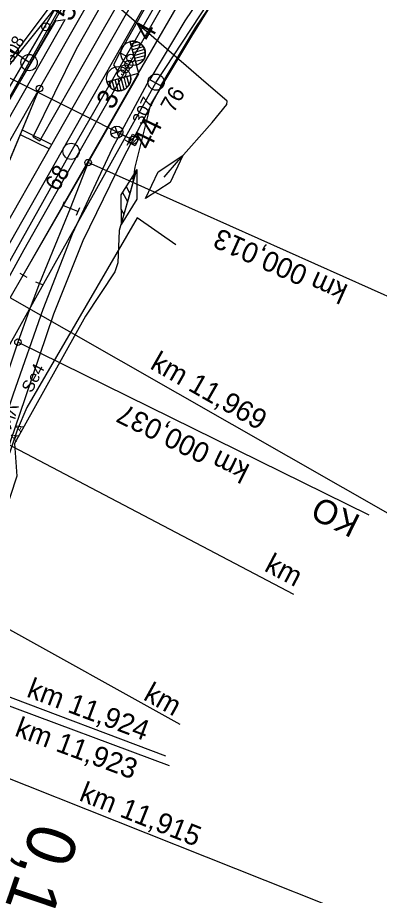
# Model space of a CAD drawing. Extents: x -598638 to -597933, y -1164002 to -1161904.
# Drawn here: x -598180.3 to -598135.8, y -1162996.2 to -1162888 of the extents above; entities that cross this region are included whole.
import ezdxf

# ---------------------------------------------------------------- set-up
doc = ezdxf.new("R2010")
doc.units = 0
for name, color, linetype in [('Vrstva 1', 7, 'Continuous'), ('Vrstva 11', 7, 'Continuous'), ('Vrstva 12', 7, 'Continuous'), ('Vrstva 17', 7, 'Continuous'), ('Vrstva 2', 7, 'Continuous'), ('Vrstva 25', 7, 'Continuous'), ('Vrstva 26', 7, 'Continuous'), ('Vrstva 28', 7, 'Continuous'), ('Vrstva 3', 7, 'Continuous'), ('Vrstva 31', 7, 'Continuous'), ('Vrstva 4', 7, 'Continuous'), ('Vrstva 43', 7, 'Continuous'), ('Vrstva 44', 7, 'Continuous'), ('Vrstva 51', 7, 'Continuous'), ('Vrstva 6', 7, 'Continuous'), ('Vrstva 63', 7, 'Continuous'), ('Vrstva 7', 7, 'Continuous')]:
    doc.layers.add(name, color=color, linetype=linetype)

msp = doc.modelspace()

# ---------------------------------------------------------------- linework, layer by layer
at = {"layer": 'Vrstva 1'}
for p, q in [((-598183.34, -1162910.45), (-598177.65, -1162896.76)), ((-598128.48, -1162925.23), (-598171.66, -1162905.9)), ((-598181.24, -1162922.58), (-598179.64, -1162919.76)), ((-598122.64, -1162956.06), (-598181.24, -1162922.58)), ((-598137.06, -1162949.35), (-598180.29, -1162928.03)), ((-598210.16, -1162970.38), (-598089.89, -1163018.24))]:
    msp.add_line(p, q, dxfattribs=at)
for points in [[(-598185.54, -1162920.23), (-598173.48, -1162899.03), (-598147.83, -1162853.98), (-598130.65, -1162823.79), (-598124.88, -1162813.62), (-598094.68, -1162760.58), (-598072.51, -1162721.65)], [(-598179.64, -1162919.76), (-598169.47, -1162901.95), (-598165.44, -1162894.88), (-598159.18, -1162883.99), (-598151.26, -1162869.97), (-598148.35, -1162864.87)], [(-598184.99, -1162909.66), (-598177.65, -1162896.76), (-598171.54, -1162886.04)], [(-598171.66, -1162905.9), (-598173.85, -1162911.56), (-598177.66, -1162920.77), (-598178.92, -1162924.14), (-598179.73, -1162926.43), (-598180.29, -1162928.03)], [(-598180.29, -1162928.03), (-598182.13, -1162933.48), (-598183.24, -1162936.76), (-598184.09, -1162939.28), (-598186.44, -1162946.2), (-598190.32, -1162957.65), (-598194.22, -1162969.2), (-598198.16, -1162980.82), (-598202.12, -1162992.49)]]:
    msp.add_lwpolyline(points, dxfattribs=at)
for centre in [(-598171.66, -1162905.9), (-598180.29, -1162928.03)]:
    msp.add_circle(centre, 0.4, dxfattribs=at)
at = {"layer": 'Vrstva 11'}
for p, q in [((-598166.55, -1162903.3), (-598165.91, -1162902.66)), ((-598166.29, -1162903.57), (-598165.64, -1162902.92))]:
    msp.add_line(p, q, dxfattribs=at)
msp.add_lwpolyline([(-598181.56, -1162895.33), (-598166.09, -1162903.12)], dxfattribs=at)
msp.add_circle((-598166.09, -1162903.12), 0.5, dxfattribs=at)
at = {"layer": 'Vrstva 12'}
msp.add_lwpolyline([(-598166.69, -1162903.41), (-598166.21, -1162902.41), (-598165.38, -1162902.84), (-598165.88, -1162903.83), (-598166.69, -1162903.41)], dxfattribs=at)
at = {"layer": 'Vrstva 17'}
msp.add_lwpolyline([(-598160.87, -1162916.03), (-598165.61, -1162912.69), (-598173.23, -1162925.77), (-598179.2, -1162936.08), (-598180.4, -1162938.88), (-598184.23, -1162950.26), (-598188.1, -1162961.63), (-598191.91, -1162973.02), (-598198.54, -1162970.75), (-598204.12, -1162984.71), (-598208.62, -1162995.88), (-598214.21, -1163009.83), (-598215.03, -1163012.69), (-598218.21, -1163027.37), (-598221.45, -1163042.04), (-598223.96, -1163053.78), (-598226.52, -1163065.42), (-598227.97, -1163080.38)], dxfattribs=at)
at = {"layer": 'Vrstva 2'}
for p, q in [((-598166.52, -1162890.98), (-598165.44, -1162894.88)), ((-598166.52, -1162890.98), (-598165.72, -1162893.87)), ((-598165.56, -1162891.04), (-598166.43, -1162891.28)), ((-598165.12, -1162891.31), (-598166.33, -1162891.64)), ((-598164.85, -1162891.62), (-598166.23, -1162892)), ((-598164.7, -1162891.97), (-598166.14, -1162892.36)), ((-598164.62, -1162892.34), (-598166.04, -1162892.72)), ((-598164.65, -1162892.73), (-598165.94, -1162893.08)), ((-598164.82, -1162893.17), (-598165.84, -1162893.45)), ((-598169.35, -1162895.95), (-598165.44, -1162894.88)), ((-598169.35, -1162895.95), (-598166.45, -1162895.16)), ((-598168.81, -1162896.74), (-598169.05, -1162895.87)), ((-598168.35, -1162896.98), (-598168.69, -1162895.77)), ((-598167.95, -1162897.05), (-598168.32, -1162895.67)), ((-598167.57, -1162897.01), (-598167.96, -1162895.57)), ((-598167.21, -1162896.88), (-598167.6, -1162895.47)), ((-598166.89, -1162896.66), (-598167.24, -1162895.37)), ((-598166.6, -1162896.29), (-598166.88, -1162895.28)), ((-598180.07, -1162919.52), (-598179.2, -1162920.01)), ((-598178.13, -1162920.58), (-598177.2, -1162920.95))]:
    msp.add_line(p, q, dxfattribs=at)
for points in [[(-598165.44, -1162894.88), (-598159.18, -1162883.99), (-598151.26, -1162869.97)], [(-598184.99, -1162909.66), (-598177.65, -1162896.76), (-598171.54, -1162886.04)], [(-598179.64, -1162919.76), (-598169.47, -1162901.95), (-598165.44, -1162894.88)], [(-598179.64, -1162919.76), (-598171.66, -1162905.9), (-598165.42, -1162894.94)], [(-598183.34, -1162910.45), (-598177.65, -1162896.76)], [(-598171.66, -1162905.9), (-598173.85, -1162911.56), (-598177.66, -1162920.77)]]:
    msp.add_lwpolyline(points, dxfattribs=at)
for centre, radius in [((-598166.12, -1162892.43), 1.5), ((-598167.9, -1162895.55), 1.5), ((-598177.65, -1162896.76), 0.4)]:
    msp.add_circle(centre, radius, dxfattribs=at)
for centre, start, end in [((-598166.12, -1162892.43), 285.4284, 105.3223), ((-598167.9, -1162895.55), 195.3744, 15.2683)]:
    msp.add_arc(centre, 1.5, start, end, dxfattribs=at)
at = {"layer": 'Vrstva 25'}
for p, q in [((-598166.45, -1162893.04), (-598166.35, -1162893.04)), ((-598167.16, -1162894.34), (-598167.06, -1162894.34)), ((-598166.69, -1162893.78), (-598166.59, -1162893.78)), ((-598167.58, -1162894.98), (-598167.48, -1162894.98)), ((-598168.85, -1162902.35), (-598167.4, -1162901.93)), ((-598168.39, -1162901.44), (-598167.84, -1162902.84)), ((-598167.44, -1162902.47), (-598166.09, -1162903.12))]:
    msp.add_line(p, q, dxfattribs=at)
for centre, radius in [((-598166.4, -1162893.04), 0.5), ((-598166.64, -1162893.78), 0.5), ((-598167.53, -1162894.98), 0.5), ((-598167.1, -1162894.34), 0.5), ((-598168.12, -1162902.14), 0.754)]:
    msp.add_circle(centre, radius, dxfattribs=at)
at = {"layer": 'Vrstva 26'}
for points in [[(-598162.29, -1162907.68), (-598160.52, -1162905.64), (-598156.39, -1162900.94), (-598154.58, -1162898.75), (-598154.55, -1162898.34), (-598157.75, -1162895.55), (-598176.73, -1162879.07), (-598179.95, -1162876.37), (-598180.59, -1162876.27), (-598182.63, -1162877), (-598185.73, -1162879.3), (-598188.68, -1162881.22)], [(-598177.39, -1162884.51), (-598175.61, -1162885.6), (-598182.4, -1162894.72)], [(-598164.59, -1162910.32), (-598163.05, -1162907.02), (-598159.99, -1162905.04), (-598161.54, -1162908.34), (-598164.59, -1162910.32)]]:
    msp.add_lwpolyline(points, dxfattribs=at)
at = {"layer": 'Vrstva 28'}
for points in [[(-598165.35, -1162868.56), (-598166.23, -1162870.7), (-598173.18, -1162882.63), (-598174.44, -1162884.86), (-598175.14, -1162886.06), (-598182.34, -1162895.13), (-598182.84, -1162898.8), (-598191.85, -1162911.77), (-598196.36, -1162918.32), (-598203.62, -1162928.28), (-598209.47, -1162938.34), (-598213.45, -1162942.95), (-598224.08, -1162958.18), (-598230.16, -1162966.29)], [(-598156.15, -1162872.45), (-598162.96, -1162883.79), (-598167.76, -1162892.32), (-598168.53, -1162893.86), (-598167.93, -1162894.78)], [(-598167.76, -1162892.32), (-598166.89, -1162892.81)]]:
    msp.add_lwpolyline(points, dxfattribs=at)
at = {"layer": 'Vrstva 3'}
for p, q in [((-598174.59, -1162910.73), (-598174.96, -1162911.65)), ((-598172.92, -1162911.94), (-598174.77, -1162911.19)), ((-598172.73, -1162911.48), (-598173.11, -1162912.4))]:
    msp.add_line(p, q, dxfattribs=at)
at = {"layer": 'Vrstva 31'}
for p, q in [((-598166.29, -1162907.71), (-598166.06, -1162908.11)), ((-598165.82, -1162907.01), (-598165.78, -1162907.13)), ((-598166.98, -1162908.83), (-598166.51, -1162909.69)), ((-598167.42, -1162909.58), (-598166.8, -1162910.7)), ((-598167.62, -1162911.6), (-598167.25, -1162912.27)), ((-598167.6, -1162913.12), (-598167.53, -1162913.25))]:
    msp.add_line(p, q, dxfattribs=at)
for points in [[(-598153.45, -1162881.4), (-598158.92, -1162890.29), (-598163.96, -1162898.74), (-598165.89, -1162906.44), (-598166.19, -1162908.57), (-598166.64, -1162910.14), (-598167.82, -1162914.28), (-598168.01, -1162918.25), (-598168.38, -1162919.35), (-598171.99, -1162924.82), (-598180.7, -1162940.52), (-598180.44, -1162944.57), (-598182.04, -1162949.43), (-598187.5, -1162961.18)], [(-598165.68, -1162906.75), (-598165.66, -1162910.42), (-598167.6, -1162913.53)]]:
    msp.add_lwpolyline(points, dxfattribs=at)
msp.add_lwpolyline([(-598165.68, -1162906.75), (-598167.62, -1162909.86), (-598167.6, -1162913.53)], close=True, dxfattribs=at)
at = {"layer": 'Vrstva 4'}
msp.add_lwpolyline([(-598189.85, -1162912.96), (-598181.36, -1162896.67), (-598172.76, -1162881.84), (-598166.71, -1162871.53), (-598158.96, -1162856.49), (-598153.45, -1162843.16), (-598148.64, -1162831.26), (-598144.35, -1162818.42), (-598142.28, -1162807.31), (-598140.14, -1162793.27), (-598139.29, -1162780.25), (-598139.05, -1162767.58), (-598140.21, -1162754.84), (-598141.4, -1162743.83), (-598143.05, -1162731.28)], dxfattribs=at)
at = {"layer": 'Vrstva 43'}
for centre in [(-598178.92, -1162893.57), (-598163.29, -1162895.98), (-598173.75, -1162904.51)]:
    msp.add_circle(centre, 1, dxfattribs=at)
at = {"layer": 'Vrstva 44'}
for points in [[(-598295.76, -1163493.48), (-598278.12, -1163452.87), (-598264.21, -1163410.56), (-598254.47, -1163367.19), (-598248.62, -1163321.58), (-598253.5, -1163320.89), (-598249.61, -1163272.58), (-598247.64, -1163222.48), (-598247.49, -1163176.78), (-598247.44, -1163130.15), (-598244.01, -1163084.17), (-598235.33, -1163037.76), (-598224.82, -1163002.56), (-598219.38, -1163002.17), (-598206.65, -1162968.49), (-598191.4, -1162936.05), (-598173.75, -1162904.51), (-598155.69, -1162873.08), (-598136.14, -1162838.45), (-598116.78, -1162804.2)], [(-598214.43, -1163003.4), (-598199.22, -1162964.02), (-598185.65, -1162936.04), (-598163.29, -1162895.98), (-598150.22, -1162876.09), (-598140.44, -1162856.73), (-598111, -1162804.44)], [(-598146.93, -1162827.55), (-598158.84, -1162857.65), (-598178.92, -1162893.57)], [(-598217.58, -1162951.29), (-598196.17, -1162924.21), (-598178.92, -1162893.57), (-598182.38, -1162891.17)]]:
    msp.add_lwpolyline(points, dxfattribs=at)
at = {"layer": 'Vrstva 51'}
for points in [[(-598178.43, -1162902.74), (-598173.08, -1162891.88), (-598150.91, -1162852.7), (-598130.37, -1162815.03), (-598129.52, -1162815.46), (-598097.65, -1162759.97), (-598075.42, -1162720.73), (-598062.42, -1162699.09), (-598047.08, -1162676.16), (-598029.93, -1162650.25)], [(-598178.43, -1162902.74), (-598177.62, -1162903.2), (-598171.58, -1162892.62), (-598149.28, -1162853.59), (-598127.95, -1162816.24), (-598096.39, -1162760.67), (-598074.05, -1162721.43), (-598061.02, -1162699.88), (-598045.71, -1162676.96), (-598028.72, -1162651.1), (-598029.93, -1162650.25)], [(-598243.76, -1163139.38), (-598243.39, -1163128.84), (-598242.66, -1163113.52), (-598241.12, -1163096.73), (-598238.54, -1163077.3), (-598236.36, -1163063.88), (-598233.01, -1163047.35), (-598229.45, -1163032.19), (-598222.57, -1163008.64), (-598216.79, -1162991.45), (-598211.31, -1162977.14), (-598198.95, -1162949.03), (-598191.95, -1162935.14), (-598181.21, -1162915.65), (-598172.37, -1162900.09), (-598146.64, -1162854.69), (-598125.44, -1162817.43), (-598123.4, -1162813.87), (-598093.87, -1162762.32), (-598071.49, -1162722.83), (-598058.73, -1162701.73), (-598043.4, -1162678.61), (-598026.17, -1162652.84)], [(-598239.09, -1163097.09), (-598236.58, -1163077.5), (-598234.31, -1163064.25), (-598231.06, -1163047.87), (-598227.33, -1163032.52), (-598220.68, -1163009.31), (-598214.85, -1162992.2), (-598209.45, -1162977.85), (-598197.19, -1162949.98), (-598190.09, -1162935.88), (-598179.54, -1162916.62), (-598170.67, -1162900.92), (-598144.79, -1162855.5), (-598123.54, -1162818.5), (-598121.57, -1162815), (-598092.21, -1162763.36), (-598069.5, -1162724.25), (-598055.71, -1162703.11), (-598040.47, -1162680.63), (-598023.35, -1162655.06), (-598026.17, -1162652.84)], [(-598155.3, -1162881.75), (-598159.75, -1162888.41), (-598164.07, -1162895.66), (-598162.71, -1162896.45), (-598158.41, -1162889.2), (-598154.04, -1162882.74)], [(-598247.16, -1162992.68), (-598248.45, -1162991.68), (-598236.17, -1162974.65), (-598221.6, -1162956.03), (-598208.36, -1162939.29), (-598201.43, -1162930.16), (-598189.85, -1162912.96), (-598180.62, -1162896.95), (-598175.62, -1162888.4), (-598174.5, -1162888.26)], [(-598247.16, -1162992.68), (-598234.98, -1162975.74), (-598220.23, -1162956.98), (-598207.08, -1162940.21), (-598200.08, -1162931.08), (-598188.9, -1162913.56), (-598179.45, -1162896.99), (-598174.5, -1162888.26)], [(-598221.48, -1163080.78), (-598219.57, -1163067.14), (-598219.22, -1163065.1), (-598216.81, -1163053.05), (-598216.31, -1163050.15), (-598213.45, -1163037.18), (-598209.25, -1163020.99), (-598206.67, -1163012.26), (-598205.89, -1163009.29), (-598205.81, -1163008.94), (-598201.91, -1162996.55), (-598193.55, -1162971.95), (-598188.76, -1162957.83), (-598185, -1162946.67), (-598180.83, -1162934.42), (-598177.19, -1162923.97), (-598173.59, -1162914.67), (-598168.64, -1162904.11), (-598164.12, -1162895.65), (-598162.66, -1162896.44)], [(-598162.66, -1162896.44), (-598167.32, -1162905.25), (-598172.29, -1162915.54), (-598175.91, -1162924.59), (-598179.43, -1162935.04), (-598183.64, -1162947.2), (-598187.44, -1162958.57), (-598192.02, -1162972.56), (-598198.81, -1162992.79), (-598204.75, -1163011.31), (-598205.21, -1163012.91), (-598207.44, -1163020.45), (-598209.82, -1163028.44), (-598211.79, -1163036.54), (-598212.57, -1163039.78), (-598214.64, -1163049.35), (-598215.47, -1163053.32), (-598217.7, -1163064.51), (-598218.1, -1163067.37), (-598220.01, -1163080.08)]]:
    msp.add_lwpolyline(points, dxfattribs=at)
at = {"layer": 'Vrstva 6'}
for p, q in [((-598146.32, -1162959.15), (-598181.72, -1162940.54)), ((-598195.34, -1162955.67), (-598160.38, -1162975.12))]:
    msp.add_line(p, q, dxfattribs=at)
at = {"layer": 'Vrstva 63'}
msp.add_line((-598215.84, -1162958.49), (-598115.28, -1162782.61), dxfattribs=at)
at = {"layer": 'Vrstva 7'}
for p, q in [((-598176.92, -1162889.16), (-598176.82, -1162889.16)), ((-598179.78, -1162901.87), (-598176.12, -1162903.66)), ((-598180.01, -1162902.43), (-598176.41, -1162904.19)), ((-598166.22, -1162903.61), (-598167.09, -1162903.12)), ((-598166.41, -1162902.93), (-598166.9, -1162903.8)), ((-598209.02, -1162961.38), (-598162.14, -1162979.02)), ((-598199.17, -1162966.28), (-598161.68, -1162980.21))]:
    msp.add_line(p, q, dxfattribs=at)
msp.add_circle((-598176.87, -1162889.16), 0.5, dxfattribs=at)

# ---------------------------------------------------------------- texts
at = {"layer": 'Vrstva 1'}
for s, height, rotation, p in [('km 000,013', 2.5, 155.9165, (-598139.52, -1162921.07)), ('km 11,969', 2.5, 330.2597, (-598164.16, -1162931.22)), ('km 000,037', 2.5, 153.7764, (-598151.6, -1162943.24)), ('KO', 3, 153.7517, (-598137.96, -1162949.52)), ('km 11,915', 2.5, 338.3037, (-598172.89, -1162984.49))]:
    msp.add_text(s, height=height, rotation=rotation, dxfattribs=at).set_placement(p)
at = {"layer": 'Vrstva 11'}
msp.add_text('44', height=2.5, rotation=64.3467, dxfattribs=at).set_placement((-598164.06, -1162904.48))
at = {"layer": 'Vrstva 2'}
for s, rotation, p in [('5', 60.3224, (-598173.79, -1162888.64)), ('4', 60.3475, (-598164.03, -1162891.1)), ('3', 60.3475, (-598168.64, -1162899.49))]:
    msp.add_text(s, height=2.5, rotation=rotation, dxfattribs=at).set_placement(p)
at = {"layer": 'Vrstva 25'}
for s, rotation, p in [('308', 62.1245, (-598180.99, -1162893.75)), ('307', 64.359, (-598164.96, -1162901.31))]:
    msp.add_text(s, height=1.5, rotation=rotation, dxfattribs=at).set_placement(p)
at = {"layer": 'Vrstva 3'}
msp.add_text('Vk1', height=1.5, rotation=251.2317, dxfattribs=at).set_placement((-598181.58, -1162935.45))
at = {"layer": 'Vrstva 43'}
for s, rotation, p in [('76', 60.3608, (-598161.13, -1162899.87)), ('68', 60.2745, (-598175.34, -1162909.55))]:
    msp.add_text(s, height=2, rotation=rotation, dxfattribs=at).set_placement(p)
at = {"layer": 'Vrstva 6'}
for s, height, rotation, p in [('Se4', 1.5, 62.2713, (-598178.61, -1162934.37)), ('  A A', 1, 62.2713, (-598180.83, -1162941.01)), ('km ', 2.5, 332.2713, (-598150.1, -1162956.17)), ('km ', 2.5, 330.9055, (-598164.99, -1162972.04))]:
    msp.add_text(s, height=height, rotation=rotation, dxfattribs=at).set_placement(p)
at = {"layer": 'Vrstva 7'}
for s, height, rotation, p in [('km 11,924', 2.5, 339.3702, (-598179.35, -1162971.7)), ('km 11,923', 2.5, 339.6146, (-598180.82, -1162976.52)), ('0,1', 6, 251.2752, (-598178.35, -1162986.97))]:
    msp.add_text(s, height=height, rotation=rotation, dxfattribs=at).set_placement(p)

doc.saveas('drawing.dxf')
